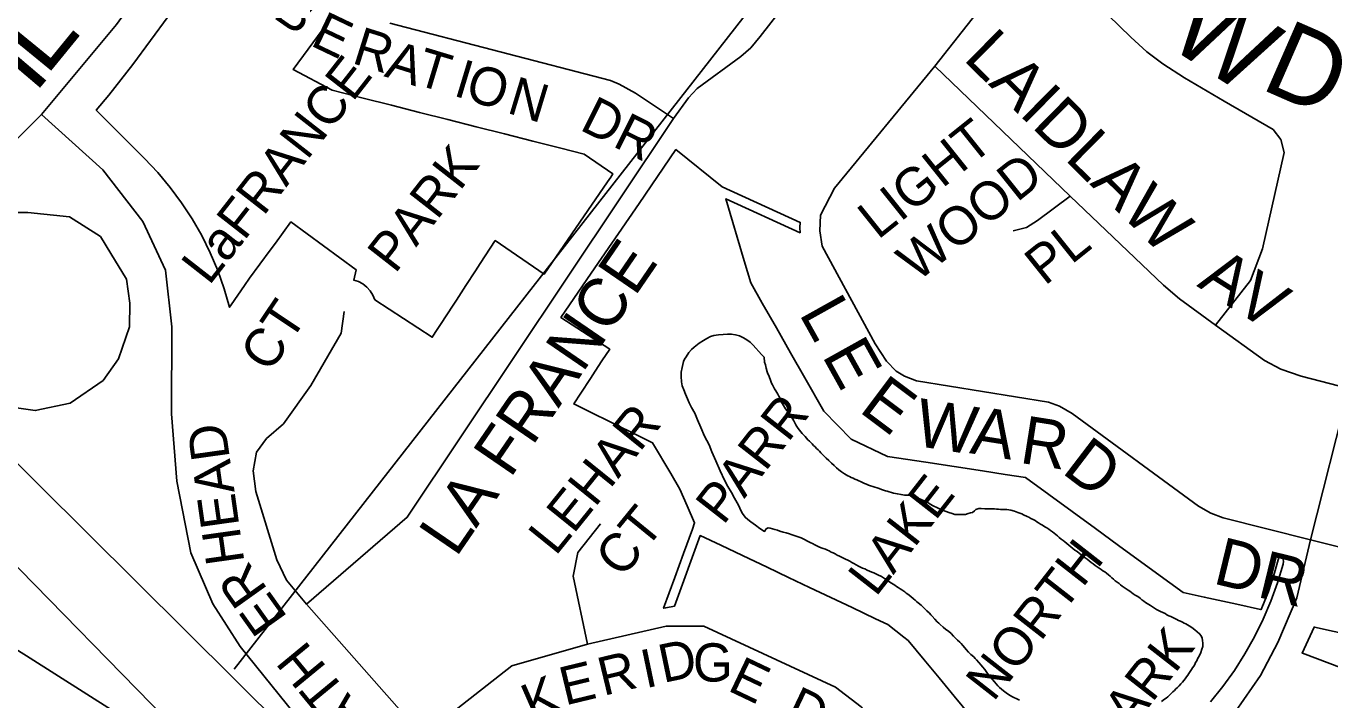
# Model space of a CAD drawing. Extents: x 586326 to 623965, y 4819854 to 4857850.
# Drawn here: x 600638 to 601319, y 4840854 to 4841206 of the extents above; entities that cross this region are included whole.
import ezdxf

# ---------------------------------------------------------------- set-up
doc = ezdxf.new("R2010")
doc.units = 0
for name, color, linetype in [('Lots_Concessions', 7, 'Continuous'), ('Major Rds and Hwys', 7, 'Continuous'), ('Major Rds Lbls', 7, 'Continuous'), ('Minor Rd Lbls', 7, 'Continuous'), ('Minor Rds', 7, 'Continuous'), ('Park Lbls', 7, 'Continuous'), ('Park Outlines', 7, 'Continuous'), ('Proposed Secondary Rds', 7, 'Continuous'), ('Secondary Rds Lbls', 7, 'Continuous')]:
    doc.layers.add(name, color=color, linetype=linetype)

msp = doc.modelspace()

# ---------------------------------------------------------------- linework, layer by layer
at = {"layer": 'Lots_Concessions'}
msp.add_line((600746.61, 4840870.14), (601547, 4841895.34), dxfattribs=at)
at = {"layer": 'Major Rds and Hwys'}
for points in [[(600645.76, 4841160.04), (600685.11, 4841207.14), (600899.6, 4841501.73), (600944.81, 4841569.11)], [(600620.94, 4841135.22), (600630.94, 4841145.22), (600645.76, 4841160.04)], [(600831.19, 4840781.02), (600749.59, 4840882.01), (600735.38, 4840904.34), (600723.82, 4840930.89), (600716.53, 4840968.39), (600713.73, 4841003.56), (600713.89, 4841049.05), (600710.65, 4841078.64), (600698.78, 4841104.2), (600677.86, 4841131.1), (600645.76, 4841160.04)], [(600578.51, 4841091.01), (600628.41, 4841108.9), (600638.7, 4841108.84), (600660.39, 4841106.61), (600676.6, 4841096.28), (600682.12, 4841087.42), (600690.18, 4841073.99), (600691.97, 4841061.46), (600691.8, 4841049.05), (600686.13, 4841032.43), (600678.02, 4841021.08), (600660.79, 4841009.13), (600642.55, 4841005.27), (600624.31, 4841007.91), (600603.35, 4841021.17), (600566.9, 4841043.32)], [(600831.19, 4840781.02), (600824.27, 4840787.89), (600566.9, 4841043.32)], [(600522.37, 4841034.99), (600550.13, 4841008.31), (600787.54, 4840765.77), (600796.42, 4840756.7)], [(600485.16, 4840997.87), (600511.95, 4840972.02), (600521.28, 4840962.91), (600530.61, 4840953.8), (600542.04, 4840944.4), (600552.85, 4840935.5), (600575.1, 4840917.21), (600585.29, 4840910.04), (600598.68, 4840900.61), (600617.24, 4840889.95), (600638, 4840877.03), (600684.35, 4840847.65), (600796.42, 4840756.7)]]:
    msp.add_lwpolyline(points, dxfattribs=at)
at = {"layer": 'Minor Rds'}
for points in [[(601100.19, 4841301.59), (601071.82, 4841265.51), (601021.4, 4841200.88), (601016.49, 4841194.98), (601011.3, 4841190.37), (600988.54, 4841173.57), (600984.06, 4841168.83), (600976.16, 4841157.89)], [(601112.7, 4841185.32), (601156.34, 4841240.78), (601160.24, 4841243.46), (601164.24, 4841244.32), (601168.94, 4841243.9), (601173.36, 4841241.19), (601215.25, 4841200.47), (601223.57, 4841192.9), (601231.9, 4841186.48), (601243.27, 4841179.19), (601263.96, 4841167.01), (601289.49, 4841152.22), (601293.55, 4841146.95), (601295.37, 4841140.26), (601284.02, 4841089.79), (601277.74, 4841073.37), (601259.47, 4841049.95)], [(600976.16, 4841157.89), (600956.27, 4841171.25), (600947.77, 4841176), (600943.2, 4841177.86), (600827.82, 4841207.83)], [(601309.04, 4840937.72), (601263.51, 4840949.32), (601256.99, 4840951.68), (601250.56, 4840955.26), (601184.48, 4841003.86), (601177.95, 4841007.67), (601172.1, 4841009.78), (601103.23, 4841020.88), (601096.9, 4841023.28), (601092.49, 4841025.95), (601087.45, 4841031.1), (601081.55, 4841040.14), (601053.78, 4841091.21), (601052.56, 4841099.32), (601052.97, 4841107.42), (601060.27, 4841121.61), (601112.7, 4841185.32)], [(601183.52, 4841117.31), (601112.7, 4841185.32)], [(600976.16, 4841157.89), (600836.98, 4840949.56), (600784.38, 4840904.12)], [(601153.67, 4841099.34), (601160.66, 4841101.05), (601166.44, 4841104.57), (601183.52, 4841117.31)], [(601259.47, 4841049.95), (601240.64, 4841063.73), (601232.2, 4841070.78), (601183.52, 4841117.31)], [(600784.38, 4840904.12), (600773.88, 4840916.71), (600768.82, 4840927.24), (600757.87, 4840963), (600756.45, 4840973.86), (600758.28, 4840983.59), (600763.48, 4840990.79), (600772.4, 4840998.44), (600786.65, 4841018.45), (600802.46, 4841045.81), (600804.08, 4841057.16)], [(601329.04, 4841016.92), (601304.15, 4841023.28), (601293.64, 4841026.89), (601285.08, 4841031.5), (601259.47, 4841049.95)], [(600931.16, 4840883.26), (600923.66, 4840918.73), (600926.09, 4840931.1), (600938.05, 4840946.09)], [(600845.95, 4840840.64), (600844.82, 4840840.5), (600839.35, 4840841.72), (600784.38, 4840904.12)], [(601095.89, 4840776.66), (601097.96, 4840813.95), (601094.36, 4840824.84), (601074.25, 4840850.43), (601060.87, 4840860.77), (600991.96, 4840892.59), (600972.31, 4840892.59), (600931.16, 4840883.26)], [(600931.16, 4840883.26), (600891.64, 4840871.91), (600852.93, 4840841.51), (600845.95, 4840840.64)]]:
    msp.add_lwpolyline(points, dxfattribs=at)
at = {"layer": 'Park Outlines'}
for points in [[(600739.67, 4841249.07), (600693.51, 4841186.25), (600687.36, 4841178.1), (600681, 4841170.13), (600674.42, 4841162.32), (600696.16, 4841140.6), (600699.73, 4841137.04), (600706.63, 4841129.71), (600713.09, 4841121.99), (600719.08, 4841113.91), (600724.58, 4841105.48), (600729.57, 4841096.74), (600734.04, 4841087.73), (600737.97, 4841078.46), (600741.35, 4841068.98), (600744.15, 4841059.32), (600745.03, 4841060.6), (600751.92, 4841070.68), (600754.5, 4841074.46), (600759.92, 4841081.83), (600765.34, 4841089.2), (600768.05, 4841092.89), (600776.16, 4841103.92), (600810.22, 4841078.9), (600809, 4841073.51), (600811.51, 4841072.71), (600813.84, 4841071.48), (600815.91, 4841069.86), (600817.67, 4841067.91), (600819.07, 4841065.67), (600820.05, 4841063.23), (600850.06, 4841043.65), (600852.69, 4841047.67), (600854.36, 4841050.23), (600861.02, 4841060.44), (600862.69, 4841062.99), (600867.69, 4841070.66), (600872.69, 4841078.31), (600875.19, 4841082.15), (600883.02, 4841094.16), (600908.58, 4841076.64), (600941.64, 4841124.91), (600943.33, 4841127.38), (600944.46, 4841129.03), (600929.38, 4841139.35), (600917.33, 4841142.4), (600902.56, 4841146.15), (600887.79, 4841149.89), (600873.02, 4841153.63), (600858.25, 4841157.37), (600843.48, 4841161.11), (600828.72, 4841164.86), (600813.95, 4841168.6), (600797.73, 4841172.71), (600777.38, 4841183.55), (600795.42, 4841208.11)], [(601256.88, 4840853.15), (601263.3, 4840861.13), (601269.28, 4840869.45), (601274.79, 4840878.09), (601279.81, 4840887.03), (601284.34, 4840896.22), (601288.34, 4840905.65), (601291.82, 4840915.29), (601294.77, 4840925.11), (601294.77, 4840925.11), (601294.94, 4840926.56), (601294.68, 4840928), (601294.02, 4840929.3), (601293.01, 4840930.35), (601290.32, 4840920.48), (601287.08, 4840910.77), (601283.29, 4840901.26), (601282.99, 4840901.33), (601270.6, 4840904.05), (601253.54, 4840907.8), (601242.47, 4840910.23), (601235.62, 4840915.25), (601220.98, 4840925.95), (601208.82, 4840934.84), (601196.66, 4840943.74), (601184.5, 4840952.63), (601172.34, 4840961.52), (601160.18, 4840970.41), (601149.53, 4840971.93), (601137.67, 4840973.75), (601122.85, 4840976.02), (601108.02, 4840978.29), (601087.96, 4840981.36), (601069.05, 4840990.34), (601054.66, 4841004.94), (601044.73, 4841022.42), (601037.32, 4841035.45), (601029.91, 4841048.49), (601022.5, 4841061.53), (601016.52, 4841072.05), (601013.1, 4841083.55), (601003.49, 4841115.91), (601042.29, 4841098.21), (601042.26, 4841100.93), (601042.41, 4841103.65), (601001.6, 4841122.26), (600977.4, 4841141.75), (600958.13, 4841113.61), (600933.14, 4841077.11), (600917.32, 4841054.02), (600942.84, 4841037.36), (600938.76, 4841031.39), (600935.21, 4841025.95), (600932.71, 4841022.13), (600927.71, 4841014.47), (600924.01, 4841008.79), (600931.76, 4841004.96), (600957.2, 4840992.4), (600965.24, 4840988.42), (600974.7, 4840972.37), (600979.5, 4840964.22), (600983.28, 4840955.59), (600987.21, 4840946.62), (600986.01, 4840943.33), (600981.4, 4840930.66), (600976.78, 4840917.99), (600970.95, 4840901.95), (600972.08, 4840902.21), (600976.67, 4840903.06), (600990.11, 4840939.98), (601000.87, 4840934.87), (601012.27, 4840929.47), (601025.08, 4840923.39), (601036.19, 4840918.11), (601047.29, 4840912.84), (601058.4, 4840907.57), (601069.51, 4840902.3), (601081.7, 4840896.51), (601088.19, 4840893.43), (601096.53, 4840886.92), (601098.77, 4840885.18), (601107.13, 4840875.03), (601114.95, 4840865.55), (601122.77, 4840856.06), (601134.5, 4840841.83)], [(601231.2, 4840853.16), (601232.8, 4840854.41), (601233.65, 4840855.06), (601234.55, 4840855.76), (601235.4, 4840856.56), (601236.25, 4840857.41), (601237.1, 4840858.21), (601237.95, 4840859.01), (601238.75, 4840859.81), (601239.55, 4840860.61), (601240.4, 4840861.51), (601241.3, 4840862.41), (601242.1, 4840863.31), (601242.85, 4840864.26), (601243.55, 4840865.16), (601244.25, 4840866.06), (601244.95, 4840866.96), (601245.55, 4840867.91), (601246.2, 4840868.91), (601246.9, 4840869.91), (601247.5, 4840870.76), (601248.05, 4840871.76), (601248.55, 4840872.66), (601249.05, 4840873.56), (601249.6, 4840874.56), (601250.1, 4840875.46), (601251, 4840877.26), (601251.7, 4840878.86), (601252.35, 4840880.51), (601252.8, 4840882.06), (601252.85, 4840883.66), (601252.7, 4840885.06), (601252.45, 4840886.41), (601252, 4840887.61), (601251.1, 4840888.61), (601249.9, 4840889.71), (601248.55, 4840890.71), (601247.1, 4840891.86), (601245.6, 4840892.86), (601243.9, 4840893.76), (601243, 4840894.21), (601242.1, 4840894.71), (601241.15, 4840895.21), (601240.15, 4840895.61), (601239.15, 4840896.06), (601238.1, 4840896.56), (601237.05, 4840897.11), (601236.05, 4840897.61), (601235.05, 4840898.01), (601234.05, 4840898.56), (601233.05, 4840899.16), (601231.95, 4840899.81), (601230.75, 4840900.31), (601229.65, 4840900.81), (601228.6, 4840901.36), (601227.55, 4840902.01), (601226.5, 4840902.71), (601225.4, 4840903.36), (601223.65, 4840904.46), (601222.8, 4840905.06), (601221.95, 4840905.71), (601221, 4840906.41), (601220.2, 4840907.11), (601219.35, 4840907.71), (601218.5, 4840908.26), (601217.45, 4840908.86), (601216.4, 4840909.56), (601215.5, 4840910.26), (601214.65, 4840910.86), (601213.75, 4840911.41), (601212.7, 4840912.06), (601211.65, 4840912.86), (601210.7, 4840913.56), (601209.85, 4840914.21), (601209, 4840914.86), (601208.05, 4840915.61), (601207.05, 4840916.36), (601206.05, 4840917.11), (601205.2, 4840917.91), (601204.4, 4840918.71), (601203.5, 4840919.51), (601202.55, 4840920.26), (601201.6, 4840921.01), (601200.6, 4840921.61), (601199.65, 4840922.21), (601198.6, 4840922.91), (601197.55, 4840923.61), (601196.5, 4840924.36), (601195.45, 4840925.16), (601194.4, 4840925.96), (601193.35, 4840926.76), (601192.35, 4840927.56), (601191.3, 4840928.36), (601190.35, 4840929.11), (601189.3, 4840929.86), (601188.15, 4840930.76), (601187.05, 4840931.61), (601186, 4840932.41), (601184.95, 4840933.21), (601183.85, 4840934.11), (601182.75, 4840935.01), (601181.7, 4840935.81), (601180.75, 4840936.61), (601179.8, 4840937.36), (601178.8, 4840938.16), (601177.8, 4840939.01), (601176.9, 4840939.81), (601176.05, 4840940.51), (601175.15, 4840941.26), (601174.2, 4840941.96), (601173.2, 4840942.66), (601172.25, 4840943.36), (601171.25, 4840943.96), (601170.15, 4840944.61), (601169.05, 4840945.36), (601167.95, 4840946.01), (601166.95, 4840946.61), (601166.05, 4840947.21), (601165.1, 4840947.81), (601164.1, 4840948.41), (601163, 4840948.96), (601161.95, 4840949.51), (601161, 4840950.01), (601159.15, 4840950.86), (601158.2, 4840951.26), (601157.15, 4840951.71), (601156.15, 4840952.11), (601154.3, 4840952.81), (601152.5, 4840953.31), (601151.5, 4840953.46), (601150.4, 4840953.51), (601149.3, 4840953.56), (601148.2, 4840953.66), (601147.15, 4840953.66), (601146.1, 4840953.71), (601145.05, 4840953.76), (601143.95, 4840953.91), (601142.85, 4840954.01), (601141.8, 4840954.01), (601140.8, 4840954.01), (601138.85, 4840953.96), (601136.9, 4840954.16), (601135.75, 4840954.16), (601134.15, 4840953.56), (601133.55, 4840952.91), (601132.45, 4840952.11), (601131.35, 4840951.86), (601130.15, 4840951.46), (601128.8, 4840951.06), (601127.4, 4840950.91), (601125.95, 4840950.96), (601124.5, 4840950.96), (601123.2, 4840951.06), (601121.85, 4840951.46), (601120.1, 4840951.96), (601118.65, 4840952.56), (601117.7, 4840952.91), (601114.55, 4840954.36), (601111.45, 4840955.76), (601108.3, 4840957.56), (601104.35, 4840959.31), (601099.9, 4840960.91), (601099.8, 4840960.91), (601098.7, 4840961.01), (601096.95, 4840961.16), (601095.1, 4840961.36), (601093.15, 4840961.71), (601092.15, 4840961.96), (601091.1, 4840962.21), (601090.05, 4840962.51), (601088.95, 4840962.81), (601087.9, 4840963.11), (601086.9, 4840963.36), (601085.85, 4840963.76), (601084.8, 4840964.11), (601083.7, 4840964.51), (601082.55, 4840964.86), (601081.45, 4840965.21), (601080.35, 4840965.56), (601079.2, 4840965.96), (601078.15, 4840966.36), (601077.05, 4840966.81), (601076, 4840967.26), (601074.95, 4840967.71), (601073.95, 4840968.16), (601072.95, 4840968.61), (601071.95, 4840969.11), (601071, 4840969.51), (601070.05, 4840969.91), (601069.05, 4840970.31), (601068.1, 4840970.76), (601067.2, 4840971.26), (601065.45, 4840972.21), (601064, 4840973.21), (601062.65, 4840974.26), (601061.3, 4840975.36), (601060.05, 4840976.56), (601058.75, 4840977.86), (601057.35, 4840979.16), (601056, 4840980.46), (601054.6, 4840981.76), (601053.9, 4840982.51), (601053.15, 4840983.26), (601052.4, 4840984.06), (601051.7, 4840984.81), (601050.95, 4840985.56), (601050.15, 4840986.36), (601049.35, 4840987.11), (601048.6, 4840987.86), (601047.2, 4840989.26), (601046.45, 4840990.06), (601045.65, 4840990.91), (601044.9, 4840991.71), (601044.15, 4840992.56), (601043.4, 4840993.36), (601042.7, 4840994.21), (601042, 4840995.06), (601041.3, 4840995.96), (601040.7, 4840996.91), (601040.15, 4840997.91), (601039.65, 4840998.91), (601039.1, 4840999.91), (601038.5, 4841000.86), (601037.9, 4841001.81), (601037.3, 4841002.76), (601036.65, 4841003.66), (601036.05, 4841004.46), (601035.35, 4841005.26), (601034.7, 4841006.16), (601034.1, 4841007.06), (601033.05, 4841008.81), (601032.6, 4841009.76), (601032.1, 4841010.81), (601031.65, 4841011.91), (601031.25, 4841012.91), (601030.75, 4841013.86), (601030.2, 4841014.81), (601029.6, 4841015.71), (601028.95, 4841016.66), (601028.4, 4841017.71), (601027.9, 4841018.71), (601027.4, 4841019.71), (601027, 4841020.71), (601026.7, 4841021.66), (601026.3, 4841022.61), (601025.9, 4841023.56), (601025.5, 4841024.56), (601025.15, 4841025.61), (601024.65, 4841027.51), (601024.2, 4841029.16), (601023.7, 4841030.56), (601023.6, 4841033.21), (601022.2, 4841034.66), (601020.7, 4841036.21), (601019.2, 4841037.91), (601017.85, 4841039.51), (601016.2, 4841041.01), (601014.45, 4841042.31), (601012.7, 4841043.36), (601010.7, 4841044.31), (601008.55, 4841044.91), (601006.35, 4841045.31), (601004.3, 4841045.31), (601002.05, 4841045.11), (600999.75, 4841044.91), (600997.2, 4841044.51), (600995.5, 4841044.11), (600993.65, 4841043.01), (600991.85, 4841041.86), (600989.5, 4841040.56), (600986.95, 4841038.46), (600985.55, 4841037.26), (600984.25, 4841035.71), (600982.85, 4841033.46), (600981.95, 4841032.21), (600981.45, 4841030.96), (600980.6, 4841027.81), (600980.2, 4841025.46), (600980.15, 4841023.06), (600980.25, 4841020.36), (600980.7, 4841018.26), (600981.6, 4841016.21), (600982.45, 4841013.96), (600983.5, 4841011.36), (600984.35, 4841009.31), (600985.55, 4841006.91), (600987.25, 4841004.01), (600988.75, 4841000.51), (600990.4, 4840996.41), (600992.3, 4840992.01), (600994.8, 4840987.46), (600996.2, 4840983.76), (600998.25, 4840979.06), (601000.6, 4840973.76), (601002.85, 4840969.01), (601004.55, 4840965.66), (601006.45, 4840962.51), (601008.05, 4840959.56), (601010.05, 4840955.91), (601011.5, 4840952.76), (601012.15, 4840951.56), (601013.6, 4840949.56), (601015, 4840948.36), (601016.6, 4840947.16), (601018.95, 4840945.41), (601021.25, 4840943.66), (601023.8, 4840942.11), (601024.65, 4840943.41), (601025.55, 4840943.96), (601026.75, 4840943.76), (601027.95, 4840943.46), (601029.15, 4840943.11), (601030.45, 4840942.71), (601031.8, 4840942.21), (601033.45, 4840941.76), (601035, 4840941.36), (601036.7, 4840940.86), (601037.65, 4840940.56), (601038.7, 4840940.21), (601039.8, 4840939.81), (601040.8, 4840939.51), (601041.85, 4840939.16), (601042.85, 4840938.76), (601043.85, 4840938.31), (601044.9, 4840937.81), (601045.85, 4840937.26), (601046.85, 4840936.76), (601047.85, 4840936.26), (601048.85, 4840935.81), (601049.95, 4840935.21), (601051.05, 4840934.56), (601052.15, 4840934.06), (601053.3, 4840933.61), (601054.4, 4840933.26), (601055.55, 4840932.86), (601056.6, 4840932.41), (601057.6, 4840931.91), (601058.6, 4840931.31), (601059.6, 4840930.86), (601060.6, 4840930.36), (601061.75, 4840929.76), (601062.85, 4840929.16), (601063.9, 4840928.66), (601065, 4840928.21), (601066.1, 4840927.71), (601067.2, 4840927.16), (601068.3, 4840926.61), (601069.4, 4840925.96), (601070.45, 4840925.36), (601071.6, 4840924.71), (601072.8, 4840924.06), (601073.95, 4840923.51), (601075, 4840923.01), (601076.1, 4840922.51), (601077.3, 4840921.91), (601078.55, 4840921.31), (601079.75, 4840920.86), (601080.85, 4840920.41), (601081.9, 4840919.96), (601083, 4840919.41), (601084.85, 4840918.56), (601086.4, 4840917.56), (601087.8, 4840916.66), (601089.3, 4840915.61), (601090.9, 4840914.51), (601091.75, 4840914.01), (601092.7, 4840913.41), (601093.65, 4840912.76), (601094.6, 4840912.16), (601095.45, 4840911.61), (601097, 4840910.56), (601097.8, 4840909.91), (601098.65, 4840909.26), (601100.2, 4840908.06), (601101.65, 4840906.91), (601102.4, 4840906.26), (601103.2, 4840905.51), (601104.1, 4840904.81), (601105.6, 4840903.51), (601107.05, 4840902.16), (601107.85, 4840901.41), (601108.55, 4840900.71), (601109.9, 4840899.36), (601110.6, 4840898.61), (601111.35, 4840897.86), (601112.7, 4840896.31), (601114, 4840894.86), (601114.8, 4840894.16), (601115.55, 4840893.41), (601117.1, 4840892.06), (601118.5, 4840890.96), (601119.85, 4840890.01), (601121.25, 4840888.76), (601122.55, 4840887.46), (601123.25, 4840886.76), (601124.65, 4840885.31), (601125.75, 4840884.26), (601126.5, 4840883.51), (601127.4, 4840882.46), (601128.5, 4840881.26), (601129.2, 4840880.46), (601130.35, 4840879.01), (601131.55, 4840877.76), (601133.05, 4840876.51), (601133.8, 4840875.76), (601134.45, 4840875.06), (601135.7, 4840873.66), (601136.95, 4840872.16), (601137.6, 4840871.41), (601138.8, 4840869.91), (601139.85, 4840868.41), (601141, 4840867.01), (601141.95, 4840865.81), (601142.9, 4840864.71), (601143.85, 4840863.51), (601144.8, 4840862.41), (601145.6, 4840861.41), (601146.55, 4840860.51), (601147.6, 4840859.66), (601148.7, 4840858.81), (601150.1, 4840857.71), (601151.7, 4840856.56), (601153.4, 4840855.71), (601154.35, 4840855.21), (601155.3, 4840854.76), (601157.05, 4840853.96)], [(601331.7, 4840887.61), (601311.23, 4840892.11), (601310.93, 4840892.17), (601307.92, 4840885.3), (601304.68, 4840878.54), (601304.96, 4840878.44), (601351.46, 4840860.94)]]:
    msp.add_lwpolyline(points, dxfattribs=at)
at = {"layer": 'Proposed Secondary Rds'}
for points in [[(601309.04, 4840937.72), (601329.04, 4841016.92)], [(601176.92, 4840785.78), (601206.55, 4840796.98), (601233.89, 4840814.48), (601251.33, 4840827.93), (601269.87, 4840848.09), (601282.87, 4840866.75), (601291.93, 4840884.07), (601301.86, 4840907.38), (601309.04, 4840937.72)], [(601416.29, 4840900.29), (601397.32, 4840910.42), (601378.22, 4840919.33), (601362.66, 4840924.41), (601309.04, 4840937.72)]]:
    msp.add_lwpolyline(points, dxfattribs=at)

# ---------------------------------------------------------------- texts
at = {"layer": 'Major Rds Lbls'}
for s, rotation, p in [('L', 50.73934, (600648.13, 4841179.58)), ('I', 49.68271, (600641.89, 4841170.3))]:
    msp.add_text(s, height=40, rotation=rotation, dxfattribs=at).set_placement(p)
at = {"layer": 'Minor Rd Lbls'}
for s, height, rotation, p in [('B', 19.99, 324.99787, (600766.21, 4841211.14)), ('E', 19.99, 334.50247, (600785.74, 4841196.42)), ('R', 19.99, 342.55283, (600807.48, 4841187.1)), ('LAIDLAW', 25.002, 315.45116, (601127.09, 4841188.94)), ('A', 19.99, 342.55283, (600824.48, 4841180.1)), ('T', 20, 343.17861, (600840.48, 4841176.1)), ('I', 20, 343.17861, (600860.48, 4841170.1)), ('O', 20, 343.17861, (600866.48, 4841168.1)), ('N', 20, 343.17861, (600888.48, 4841161.1)), ('DR', 19.998, 333.43497, (600926.49, 4841152.38)), ('LIGHT', 19.998, 38.65983, (601082.98, 4841094.27)), ('WOOD', 19.998, 38.65983, (601103.48, 4841072.1)), ('PL', 19.998, 38.65983, (601170.19, 4841070.2)), ('LA FRANCE', 24.99, 55.58355, (600862.48, 4840928.1)), ('AV', 25.002, 327.61934, (601249.29, 4841070.51)), ('L', 25, 299.14809, (601041.48, 4841056.1)), ('CT', 19.998, 56.192, (600765.15, 4841024.42)), ('E', 25, 299.14809, (601053.48, 4841034.1)), ('E', 25, 323.13012, (601072.48, 4841005.1)), ('W', 25, 350.9807, (601101.48, 4840987.1)), ('LEHAR', 19.998, 51.08231, (600914.53, 4840928.88)), ('A', 25, 350.9807, (601130.48, 4840983.1)), ('R', 25, 350.9807, (601156.48, 4840978.1)), ('HEAD', 19.998, 97.99136, (600751.95, 4840926.04)), ('D', 25, 322.63335, (601178.48, 4840973.1)), ('CT', 19.998, 50.7945, (600949.34, 4840917.13)), ('D', 25, 346.32871, (601257.48, 4840915.1)), ('R', 25, 346.32871, (601280.48, 4840908.1)), ('ER', 19.998, 125.48394, (600774.81, 4840897.09)), ('LEATH', 19.998, 129.46888, (600837.88, 4840819.38)), ('D', 20, 11.82151, (600970.75, 4840862.89)), ('G', 20, 0.00002, (600986.34, 4840863.65)), ('R', 20, 13.57045, (600939.48, 4840856.1)), ('I', 20, 11.82151, (600961.48, 4840860.1)), ('E', 20, 334.53667, (601003.83, 4840859.27)), ('E', 20, 13.57045, (600919.48, 4840851.1)), ('K', 20, 23.6294, (600902.48, 4840842.1)), ('D', 20, 334.53667, (601033.34, 4840843.65))]:
    msp.add_text(s, height=height, rotation=rotation, dxfattribs=at).set_placement(p)
at = {"layer": 'Park Lbls'}
for s, p in [('LaFRANCE', (600733.43, 4841070.24)), ('PARK', (600830.6, 4841076.37)), ('PARR', (601002.15, 4840944.95)), ('LAKE', (601081.86, 4840907.47)), ('NORTH', (601143.35, 4840852.64)), ('PARK', (601204.35, 4840824.2))]:
    msp.add_text(s, height=19.992, rotation=52.00002, dxfattribs=at).set_placement(p)
at = {"layer": 'Secondary Rds Lbls'}
for s, rotation, p in [('W', 327.26479, (601232.48, 4841197.1)), ('D', 336.37064, (601282.1, 4841173.82))]:
    msp.add_text(s, height=40, rotation=rotation, dxfattribs=at).set_placement(p)

doc.saveas('drawing.dxf')
